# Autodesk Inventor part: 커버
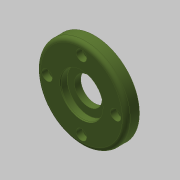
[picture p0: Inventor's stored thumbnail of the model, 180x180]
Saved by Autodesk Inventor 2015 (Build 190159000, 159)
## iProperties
Created: 2016-06
Part Number: 커버
Material: 알루미늄 6061
Document SubType Name: Modeling
Designer: mduedu
Density: 2.71 g/cm^3
Appearance: 올리브 녹색
Author: mduedu
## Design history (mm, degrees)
sketch "스케치1"
  geometry: C1 r 34 at (0, 0); 1 further point
  constraints: 1 centre point, 1 coincident
  dimensions: "d0" = 68 diameter of C1
extrude "돌출1" new body sketch "스케치1" distance "d2" = 10; taper "d3" = 0 deg
sketch "스케치2"
  geometry: C1 r 21 at (0, 0); 1 further point
  constraints: 1 centre point, 1 coincident
  dimensions: "d4" = 42 diameter of C1
extrude "돌출2" join sketch "스케치2" distance "d6" = 3; taper "d7" = 0 deg
fillet "모깎기1" dims "d8" = 3
hole "구멍1" diameter "d11" = 35; stored, may be unused: countersink angle "d15" = 90 deg, drill point angle "d17" = 0 deg; dims "d9" = 10, "d10" = 10, "d12" = 6, "d13" = 4, "d14" = 2, "d16" = 3
hole "구멍2" diameter "d20" = 32; stored, may be unused: countersink angle "d24" = 90 deg, drill point angle "d26" = 0 deg; dims "d21" = 6, "d22" = 4, "d23" = 2, "d25" = 5.2, "d46" = 10, "d47" = 10
hole "구멍3" diameter "d29" = 21; stored, may be unused: countersink angle "d33" = 90 deg, drill point angle "d35" = 0 deg; dims "d27" = 10, "d28" = 10, "d30" = 6, "d31" = 4, "d32" = 2, "d34" = 5
fillet "모깎기2" dims "d36" = 3
fillet "모깎기3" dims "d37" = 0.1
chamfer "모따기1" distance "d38" = 0.75; stored, may be unused: second distance "d39" = 2, angle "d40" = 30 deg
chamfer "모따기2" distance "d42" = 0.5; stored, may be unused: second distance "d43" = 2, angle "d44" = 30 deg
sketch "스케치3" dims "d48" = 52
  geometry: 6 further points
  constraints: 2 vertical alignment, 1 coincident, 7 other
  dimensions: "d51" = 360 deg dimension on point (0, 0) point (0, 26) (derived)
sketch "스케치4"
  geometry: 4 further points
hole "구멍4" sketch "스케치4" at (0, 26), (-26, 0), (0, -26), (26, 0) diameter "d53" = 4.5; stored, may be unused: countersink angle "d57" = 90 deg, drill point angle "d59" = 0 deg; dims "d54" = 6, "d55" = 8, "d56" = 4.6, "d58" = 8
node "솔리드1"
